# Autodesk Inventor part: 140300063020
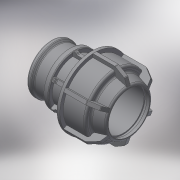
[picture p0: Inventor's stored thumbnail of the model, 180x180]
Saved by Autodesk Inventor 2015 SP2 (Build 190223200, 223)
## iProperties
Created: 2017-08
Part Number: 140300063020
Material: Generic
Description: PLASSON L.14 FEMALE ADAPTOR (SILVER) 63-2"
Document SubType Name: Modeling
Designer: KIM
Density: 1 g/cm^3
Appearance: Default
Author: KIM
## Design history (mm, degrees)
derived "140300.ipt"
feature "Solid1::140300.ipt"
tag "TaggingFeature1"
body "Solid1"
other parameters: "d1" = 63, "d2" = 86, "d4" = 15 deg, "d5" = 56.76, "d6" = 18.7308, "d9" = 56.656, "d10" = 106, "d11" = 73.6528, "d12" = 67.9872, "d13" = 79.3184, "d16" = 64.26, "d17" = 4.3, "d18" = 119, "d19" = 9, "d20" = 135 deg, "d21" = 9, "d22" = 67.9872, "d23" = 56.7, "d24" = 4.3, "d25" = 95.4, "d26" = 79.5, "d27" = 4.3, "d28" = 135 deg, "d29" = 2.58, "d31" = 3.15, "d44" = 1.26, "d45" = 1.89, "d46" = 150 deg, "d49" = 5.3, "d50" = 0, "d51" = 1.06, "d52" = 2.12, "d53" = 45 deg, "d55" = 11, "d56" = 5.3, "d57" = 0, "d58" = 1.89, "d61" = 360 deg, "d_" = 63, "G_" = 56.656, "E_" = 106, "H_" = 119, "l_" = 86, "d54" = 27.5
